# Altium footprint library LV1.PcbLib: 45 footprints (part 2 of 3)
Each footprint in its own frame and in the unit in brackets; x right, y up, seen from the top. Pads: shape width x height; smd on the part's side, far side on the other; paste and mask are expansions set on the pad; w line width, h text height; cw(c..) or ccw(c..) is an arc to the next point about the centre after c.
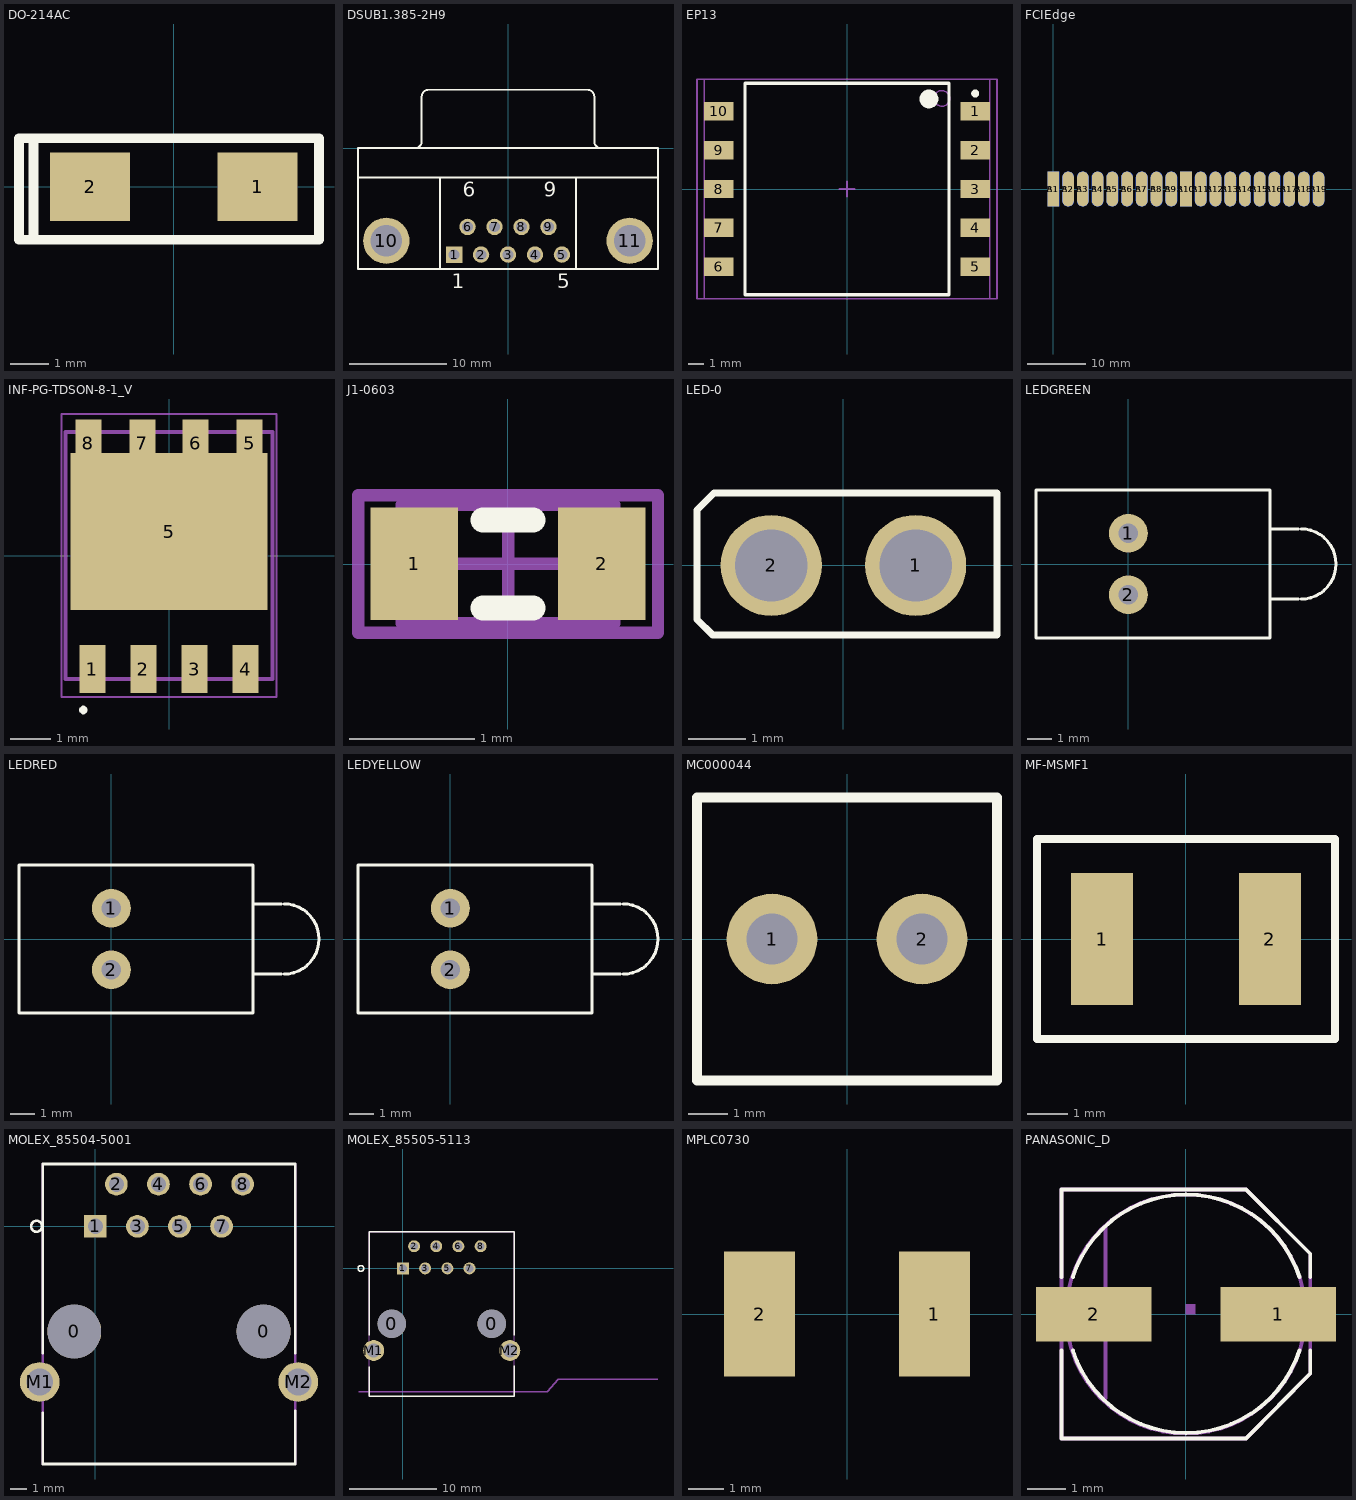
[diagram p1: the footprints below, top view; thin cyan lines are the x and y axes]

## DO-214AC [mm] "LED; 2 Leads"
height 8.6
pads (2):
  rect 2.1x1.8 smd: 1(2.2,0) 2(-2.2,0)
Top Overlay:
  lines w0.254: -3.683,-1.397 3.81,-1.397 3.81,1.27 -3.683,1.27 ; -3.683,-1.397 -3.683,1.27 ; -3.683,-1.397 -4.064,-1.397 -4.064,1.27 -3.683,1.27

## DSUB1.385-2H9 [mm] "Connector; D Subminiature; 9 Position; Right Angle; Pitch 1.385 mm"
height 12.75
pads (11):
  rect 1.69x1.69 hole 1.09: 1(-5.54,-10.92)
  round 1.69 hole 1.09: 2(-2.77,-10.92) 3(0,-10.92) 4(2.77,-10.92) 5(5.54,-10.92) 6(-4.155,-8.08) 7(-1.385,-8.08) 8(1.385,-8.08) 9(4.155,-8.08)
  round 4.76 hole 3.26: 10(-12.495,-9.5) 11(12.495,-9.5)
Top Overlay:
  lines w0.2: -15.4,-3 15.4,-3 ; -9.56,0.005 ccw(c-9.56,0.7) -8.865,0.7 -8.865,5.3 ; -8.86,5.305 cw(c-8.165,5.305) -8.165,6 8.165,6 cw(c8.165,5.305) 8.86,5.305 ; -7,-12.4 -7,-3 ; 7,-12.4 7,-3 ; 8.865,5.3 8.865,0.7 ccw(c9.56,0.7) 9.56,0.005 ; -15.4,-12.4 15.4,-12.4 15.4,0 -15.4,0 -15.4,-12.4
  text "6" at -4.655,-4.975 h1.5
  text "9" at 3.655,-4.975 h1.5
  text "5" at 5.04,-14.375 h1.5
  text "1" at -5.79,-14.375 h1.5
3D body "182-009-213.STEP": height 12.55, standoff -3.17, extent -15.278,-12.852 15.532,6.223

## EP13 [mm] "SMD, 10-Leads, Body 13.5x14.0mm (max), Pitch 2.48mm, IPC Medium Density"
height 12.7
pads (10):
  rect 1.88x1.17 smd: 1(8.18,4.96) 2(8.18,2.48) 3(8.18,0) 4(8.18,-2.48) 5(8.18,-4.96) 6(-8.18,-4.96) 7(-8.18,-2.48) 8(-8.18,0) 9(-8.18,2.48) 10(-8.18,4.96)
Top Overlay:
  circle w0.6: c5.23,5.75 r0.3
  circle w0.25: c8.18,6.095 r0.125
  lines w0.2: -6.5,-6.75 6.5,-6.75 6.5,6.75 -6.5,6.75 -6.5,-6.75
Mechanical 13:
  circle w0.1: c6.05,5.78 r0.5
  lines w0.1: -9.1,-7 9.1,-7 9.1,7 -9.1,7 -9.1,-7
Mechanical 15:
  lines w0.1: -0.5,0 0.5,0 ; 0,-0.5 0,0.5 ; -9.575,-7 9.575,-7 9.575,7 -9.575,7 -9.575,-7
3D body "WE-FB_EP13.stp": height 12.5, standoff 0, extent -8.875,-6.75 8.875,6.75

## FCIEdge [mm]
pads (38):
  rect 2x6 smd: A1(0,0) A10(22.86,0)
  oval 2x6 smd: A2(2.54,0) A3(5.08,0) A4(7.62,0) A5(10.16,0) A6(12.7,0) A7(15.24,0) A8(17.78,0) A9(20.32,0) A11(25.4,0) A12(27.94,0) A13(30.48,0) A14(33.02,0) A15(35.56,0) A16(38.1,0) A17(40.64,0) A18(43.18,0) A19(45.72,0)
  rect 2x6 smd far side: B1(0,0) B10(22.86,0)
  oval 2x6 smd far side: B2(2.54,0) B3(5.08,0) B4(7.62,0) B5(10.16,0) B6(12.7,0) B7(15.24,0) B8(17.78,0) B9(20.32,0) B11(25.4,0) B12(27.94,0) B13(30.48,0) B14(33.02,0) B15(35.56,0) B16(38.1,0) B17(40.64,0) B18(43.18,0) B19(45.72,0)

## INF-PG-TDSON-8-1_V [mm] "TDSON, 8-Leads, Body 6.15x5.15mm, Pitch 1.27mm"
height 1
pads (9):
  rect 0.65x1.2 smd: 1(-1.905,-2.825) 2(-0.635,-2.825) 3(0.635,-2.825) 4(1.905,-2.825) 5(2.007,2.794) 6(0.66,2.794) 7(-0.66,2.794) 8(-2.007,2.794)
  rect 4.9x3.9 smd: 5(0,0.6)
Top Overlay:
  region: -2.234,-3.842 -2.234,-3.862 -2.218,-3.899 -2.19,-3.927 -2.153,-3.942 -2.134,-3.942 -2.114,-3.942 -2.077,-3.927 -2.049,-3.899 -2.034,-3.862 -2.034,-3.842 -2.034,-3.822 -2.049,-3.785 -2.077,-3.757 -2.114,-3.742 -2.134,-3.742 -2.153,-3.742 -2.19,-3.757 -2.218,-3.785 -2.234,-3.822
Mechanical 13:
  lines w0.1: -2.575,-3.075 -2.575,3.075 2.575,3.075 2.575,-3.075 -2.575,-3.075
Mechanical 15:
  lines w0.05: -2.675,-3.525 -2.675,3.525 2.675,3.525 2.675,-3.525 -2.675,-3.525
  lines w0.1: -0.5,0 0.5,0 ; 0,-0.5 0,0.5
3D body: height 1, standoff 0, extent -2.575,-3.075 2.575,3.075

## J1-0603 [mm] "Chip Resistor, Body 1.6x0.8mm, IPC High Density"
height 0.9
pads (2):
  rect 0.7x0.9 smd: 1(-0.75,0) 2(0.75,0)
Top Overlay:
  lines w0.2: -0.2,-0.35 0.2,-0.35 ; -0.2,0.35 0.2,0.35
Mechanical 13:
  lines w0.1: -0.85,-0.475 -0.85,0.475 0.85,0.475 0.85,-0.475 -0.85,-0.475
Mechanical 15:
  lines w0.1: -0.475,0 0.475,0 ; 0,-0.475 0,0.475 ; -1.2,-0.55 -1.2,0.55 1.2,0.55 1.2,-0.55 -1.2,-0.55
3D body: height 0.9, standoff 0, extent -0.85,-0.475 0.85,0.475

## LED-0 [mil] "LED; 2 Leads"
height 280.31
pads (2):
  round 70 hole 50: 1(50,0) 2(-50,0)
Top Overlay:
  lines w5: -101.38,-37.4 -90.55,-48.23 106.3,-48.23 106.3,50.2 -89.57,50.2 -101.38,38.39 -101.38,-37.4

## LEDGREEN [mm] "LED; 2 Leads"
pads (2):
  round 1.6 hole 0.8: 1(0,1.27) 2(0,-1.27)
Top Overlay:
  lines w0.127: 5.924,-1.45 7.024,-1.45 ; 5.924,1.45 7.024,1.45 ; 7.112,-1.45 ccw(c7.112,0) 7.112,1.45 ; -3.81,-3.048 5.842,-3.048 5.842,3.048 -3.81,3.048 -3.81,-3.048
3D body "5500407F.stp": height 5.97, standoff -3.68, extent -3.758,-3.048 8.636,2.921

## LEDRED [mm] "LED; 2 Leads"
pads (2):
  round 1.6 hole 0.8: 1(0,1.27) 2(0,-1.27)
Top Overlay:
  lines w0.127: 5.924,-1.45 7.024,-1.45 ; 5.924,1.45 7.024,1.45 ; 7.112,-1.45 ccw(c7.112,0) 7.112,1.45 ; -3.81,-3.048 -3.81,3.048 5.842,3.048 5.842,-3.048 -3.81,-3.048
3D body "5500407F_red.stp": height 5.97, standoff -3.68, extent -3.758,-3.048 8.636,2.921

## LEDYELLOW [mm] "LED; 2 Leads"
pads (2):
  round 1.6 hole 0.8: 1(0,1.27) 2(0,-1.27)
Top Overlay:
  lines w0.127: 5.924,-1.45 7.024,-1.45 ; 5.924,1.45 7.024,1.45 ; 7.112,-1.45 ccw(c7.112,0) 7.112,1.45 ; -3.81,-3.048 5.842,-3.048 5.842,3.048 -3.81,3.048 -3.81,-3.048
3D body "5500407F_yellow.stp": height 5.97, standoff -3.68, extent -3.758,-3.048 8.636,2.921

## MC000044 [mm]
height 7.12
pads (2):
  round 2.3 hole 1.3: 1(-1.905,0) 2(1.905,0)
Top Overlay:
  lines w0.254: -3.81,-3.6 3.81,-3.6 3.81,3.6 -3.81,3.6 -3.81,-3.6

## MF-MSMF1 [mm]
height 7.12
pads (2):
  rect 1.55x3.3 smd: 1(-2.1,0) 2(2.1,0)
Top Overlay:
  lines w0.2: -3.725,-2.5 3.725,-2.5 3.725,2.5 -3.725,2.5 -3.725,0 -3.725,-2.5

## MOLEX_85504-5001 [mil]
pads (12):
  round 128 hole 128: 0(-50,-250) 0(400,-250)
  rect 54x54 hole 36: 1(0,0)
  round 54 hole 36: 2(50,100) 3(100,0) 4(150,100) 5(200,0) 6(250,100) 7(300,0) 8(350,100)
  round 94.5 hole 63: M1(-131.89,-370.08) M2(482,-370.08)
Top Overlay:
  circle w6: c-139.76,0 r13
  lines w6: -125,-442.91 -125,-564.96 475,-564.96 475,-438.98 ; -125,-301.18 -125,148 -118.11,148 ; -120.08,148 -118.11,148 ; 475,-301.18 475,148 -118.11,148
Mechanical 2:
  text ">Name" at 44,180 h77.5
Mechanical 4:
  text ">Value" at 56,-637.8 h77.5
Mechanical 16:
  lines w5: -125,-564.96 475,-564.96 475,148 -125,148 -125,-564.96
3D body "855055113.stp": height 511.81, standoff -129.92, extent -156.77,-580.16 496.77,160

## MOLEX_85505-5113 [mil]
pads (12):
  round 128 hole 128: 0(-50,-250) 0(400,-250)
  rect 54x54 hole 36: 1(0,0)
  round 54 hole 36: 2(50,100) 3(100,0) 4(150,100) 5(200,0) 6(250,100) 7(300,0) 8(350,100)
  round 94.5 hole 63: M1(-131.89,-370.08) M2(482,-370.08)
Top Overlay:
  circle w6: c-189.76,0 r13
  lines w6: -151.77,-442.91 -151.77,-575.98 502,-575.98 502,-438.98 ; -151.77,-301.18 -151.77,165 -118.11,165 502,165 502,-301.18
Mechanical 2:
  text ">Name" at 44,180 h77.5
Mechanical 4:
  text ">Value" at 56,-637.8 h77.5
Mechanical 14:
  lines w6: -200,-557.09 650,-557.09 700,-500 1150,-500
  text "PCB Edge" at 750,-500 h77.5
Mechanical 16:
  lines w5: -151.77,-575.98 -151.77,165 502,165 502,-575.98 -151.77,-575.98
3D body "855055113.stp": height 511.81, standoff -129.92, extent -148.54,-580.08 505,160.08

## MPLC0730 [mm]
height 7.12
pads (2):
  rect 2x3.5 smd: 1(2.45,0) 2(-2.45,0)
3D body: height 2, standoff 0, extent -3.175,-2.667 3.175,2.794

## PANASONIC_D [mil]
height 280.31
pads (2):
  rect 119x56 smd: 1(95,0) 2(-94.49,0)
Top Overlay:
  lines w4: -127.95,-37.4 -127.95,-127.95 62,-127.95 128,-61.02 128,-37.4 ; -127.95,38 -127.95,128 62,128 128,62 128,38 ; -116.14,-37.4 ccw(c0.43,0.14) 117,-37.4 ; -116.14,38 cw(c0.43,0.46) 117,38
Mechanical 16:
  circle w4: c0,0 r123
  rectangle: -143.7,-13.78 -120.08,14
  rectangle: 121,-13.78 144,14
  region: 0,0 10,0 10,10 0,10
  lines w4: -82.68,-86.61 -82.68,89 ; -127.95,-127.95 62,-127.95 128,-61.02 128,62 62,128 -127.95,128 -127.95,-127.95
3D body: height 236.22, standoff 39.37, extent -119.68,-117.88 115.61,117.88
3D body: height 39.37, standoff 0, extent -130,-125 125,125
